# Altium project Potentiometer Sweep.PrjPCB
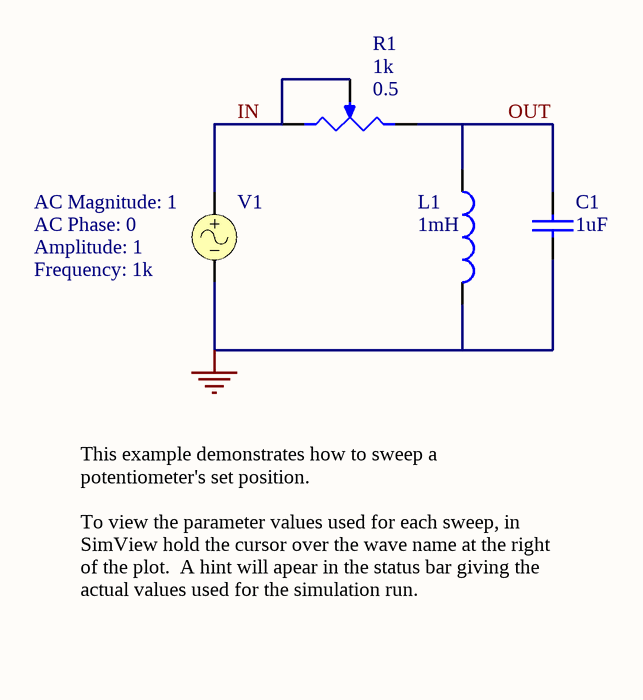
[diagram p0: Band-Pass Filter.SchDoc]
1 sheet, 4 parts. Net scope: global (net labels, ports and power ports of the same name join across sheets).

## Sheet Band-Pass Filter.SchDoc: Band-Pass Filter
size A4; Organization: Altium Limited; Address1: L3, 12a Rodborough Rd; Address2: Frenchs Forest; Address3: NSW; Address4: Australia 2086; DocumentNumber: 1; SheetNumber: 1; SheetTotal: 1

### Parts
C1  value 1uF  (hidden comment: CAP)
L1  value 1mH  (hidden comment: INDUCTOR)
R1  value 1k  Set Position: 0.5  (hidden comment: RPOT)
V1  AC Magnitude: 1  AC Phase: 0  Frequency: 1k  (hidden comment: VSIN)

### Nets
GND: C1.2 L1.2 V1.2
IN: R1.2(BOT) R1.3(TAP) V1.1
OUT: C1.1 L1.1 R1.1(TOP)

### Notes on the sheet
- This example demonstrates how to sweep a potentiometer's set position.
  To view the parameter values used for each sweep, in SimView hold the cursor over the wave name at the right of the plot.  A hint will apear in the status bar giving the actual values used for the simulation run.

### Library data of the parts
C1 = CAP: Capacitor
R1 = RPOT: Potentiometer
V1 = VSIN: Sinusoidal Voltage Source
